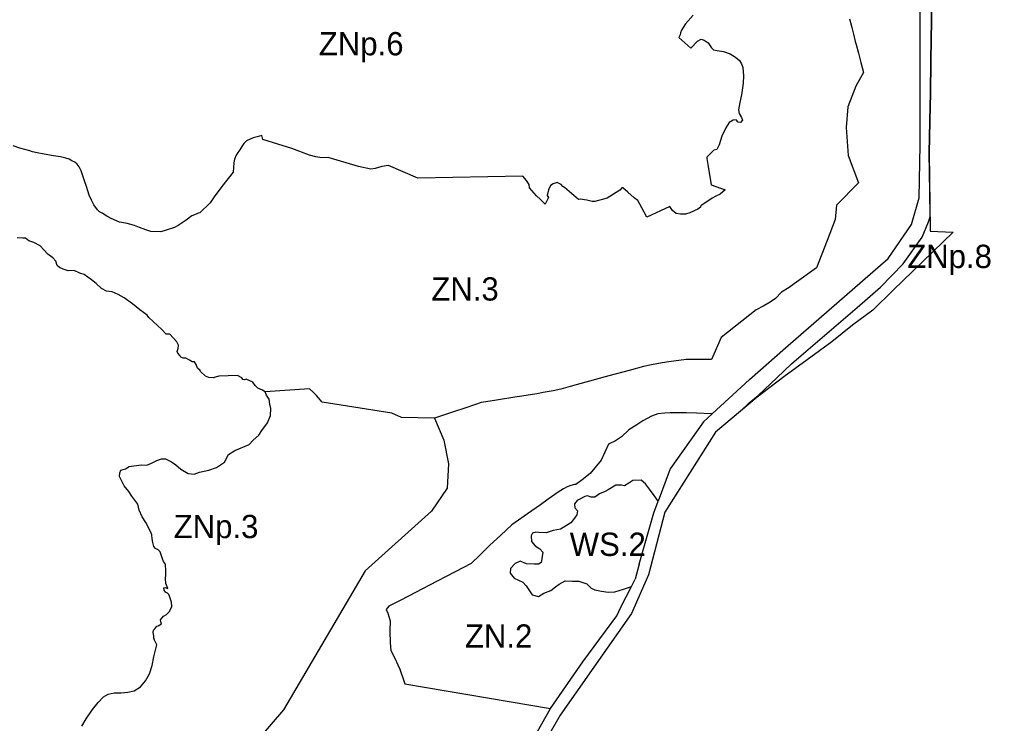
# Model space of a CAD drawing. Extents: x 7421614 to 7422630, y 5544623 to 5545754.
# Drawn here: x 7422069.4 to 7422486.7, y 5545170.9 to 5545473.4 of the extents above; entities that cross this region are included whole.
import ezdxf

# ---------------------------------------------------------------- set-up
doc = ezdxf.new("R2010")
doc.units = 0
for name, color, linetype in [('LIN_Granica Planu', 7, 'Continuous'), ('LIN_Linie Rozgraniczajace', 7, 'Continuous'), ('TXT_Oznaczenia Przeznaczenia', 7, 'Continuous')]:
    doc.layers.add(name, color=color, linetype=linetype)

msp = doc.modelspace()

# ---------------------------------------------------------------- linework, layer by layer
at = {"layer": 'LIN_Granica Planu'}
for p, q in [((7422460.78, 5545436.26), (7422460.37, 5545416.02)), ((7422427.39, 5545342.07), (7422418.45, 5545334.87)), ((7422368.51, 5545296.04), (7422346.72, 5545261.75)), ((7422332.36, 5545218.13), (7422316.17, 5545195.05))]:
    msp.add_line(p, q, dxfattribs=at)
for points in [[(7422461.42, 5545481.65), (7422461.07, 5545455.71), (7422460.88, 5545441.2), (7422460.78, 5545436.26)], [(7422460.37, 5545416.02), (7422460.82, 5545382.36), (7422470.69, 5545382.03), (7422453.28, 5545365.28), (7422444.93, 5545357.05)], [(7422444.93, 5545357.05), (7422436.2, 5545348.51), (7422427.39, 5545342.07)], [(7422418.45, 5545334.87), (7422407.86, 5545327.11), (7422397.93, 5545319.79)], [(7422397.93, 5545319.79), (7422386.41, 5545311.11), (7422368.51, 5545296.04)], [(7422346.72, 5545261.75), (7422339.71, 5545234.8), (7422332.36, 5545218.13)], [(7422316.17, 5545195.05), (7422301.74, 5545174.54), (7422292.28, 5545158.01), (7422284.38, 5545142.54)]]:
    msp.add_lwpolyline(points, dxfattribs=at)
at = {"layer": 'LIN_Linie Rozgraniczajace'}
for p, q in [((7422363.33, 5545300.54), (7422367.05, 5545303.95)), ((7422342.05, 5545261.33), (7422343.92, 5545266.38)), ((7422335.75, 5545239.39), (7422342.05, 5545261.33)), ((7422335.75, 5545239.39), (7422334.03, 5545232.88))]:
    msp.add_line(p, q, dxfattribs=at)
for points in [[(7422367.05, 5545303.95), (7422383.15, 5545318.71), (7422398.64, 5545332.29), (7422442.74, 5545370.72), (7422452.73, 5545385.22), (7422455.99, 5545396.69), (7422456.5, 5545419.48), (7422456.51, 5545483.33), (7422455.04, 5545509.49), (7422458.65, 5545526.65)], [(7422460.73, 5545388.57), (7422460.59, 5545399.19), (7422460.37, 5545416.02), (7422460.78, 5545436.26), (7422460.88, 5545441.2), (7422461.07, 5545455.71), (7422461.42, 5545481.65), (7422460.34, 5545503.62), (7422459.49, 5545515.13), (7422458.65, 5545526.65)], [(7422358.86, 5545475.17), (7422355.63, 5545471.42), (7422353.87, 5545468.71), (7422353.46, 5545467.56), (7422353.3, 5545466.78), (7422352.8, 5545465.63), (7422357.97, 5545461.05), (7422357.99, 5545461.07), (7422360.74, 5545463.97), (7422362.33, 5545464.82), (7422363.71, 5545464.4), (7422365.3, 5545463.29), (7422366.75, 5545461.15), (7422367.62, 5545460.32), (7422369.3, 5545459.95), (7422372.03, 5545459.55), (7422374.85, 5545458.61), (7422377.15, 5545457.12), (7422378.8, 5545455.66), (7422379.73, 5545454.24), (7422380.26, 5545452.67), (7422380.57, 5545449.1), (7422380.41, 5545446.03), (7422379.67, 5545440.91), (7422379.04, 5545437.7), (7422378.46, 5545434.53), (7422378.64, 5545432.97), (7422379.67, 5545431.16), (7422380.07, 5545430.04), (7422379.2, 5545429.06), (7422378.31, 5545429.26), (7422377.44, 5545430.17), (7422376.05, 5545430.03), (7422374.45, 5545429.1), (7422372.92, 5545426.8), (7422371.31, 5545423.19), (7422370.1, 5545419.47), (7422369.07, 5545417.52), (7422367.82, 5545417.2), (7422364.78, 5545414.21), (7422364.8, 5545413.67), (7422365.27, 5545411.09), (7422366.66, 5545402.3), (7422372.67, 5545400.15), (7422370.49, 5545398.35), (7422368.61, 5545397.45), (7422367.09, 5545396.56), (7422362.29, 5545393.26), (7422362.03, 5545392.66), (7422360.88, 5545391.84), (7422357.55, 5545390.27), (7422355.62, 5545389.72), (7422353.51, 5545389.64), (7422351.62, 5545390.03), (7422350.02, 5545391.26), (7422348.88, 5545392.96), (7422338.96, 5545388.41), (7422336.92, 5545392.39), (7422335.09, 5545395.57), (7422333.57, 5545396.69), (7422330.82, 5545399.11), (7422328.65, 5545400.99), (7422328.36, 5545401.22), (7422327.45, 5545400.08), (7422325.86, 5545399.07), (7422321.91, 5545396.61), (7422316.71, 5545395.14), (7422315.48, 5545395.09), (7422313.18, 5545395.7), (7422310.37, 5545396.18), (7422309.62, 5545396.07), (7422303.57, 5545401.16), (7422302.91, 5545401.6), (7422302.16, 5545402.43), (7422300.45, 5545403.35), (7422298.72, 5545402.77), (7422297.67, 5545402.05), (7422296.75, 5545400.21), (7422296.25, 5545397.79), (7422296.74, 5545396.8), (7422295.34, 5545393.99), (7422293.31, 5545396.03), (7422291.58, 5545397.52), (7422288.65, 5545401.06), (7422288.4, 5545402.39), (7422287.37, 5545404.2), (7422285.7, 5545406.01), (7422240.66, 5545405.21), (7422228.01, 5545410.64), (7422225.2, 5545410.13), (7422222.28, 5545409.26), (7422220.34, 5545409.03), (7422215.08, 5545410.11), (7422202.02, 5545413.99), (7422199.33, 5545413.95), (7422196.72, 5545414.35), (7422194.02, 5545415.11), (7422186.51, 5545417.86), (7422180.38, 5545419.78), (7422174.05, 5545421.85), (7422173.52, 5545423.49), (7422171.53, 5545422.93), (7422169.86, 5545422.54), (7422167.01, 5545421.26), (7422165.87, 5545420.13), (7422164.91, 5545418.74), (7422164.13, 5545417.33), (7422163.21, 5545416.17), (7422162.55, 5545415.11), (7422161.88, 5545413.28), (7422161.48, 5545411.76), (7422161.48, 5545411.76), (7422161.19, 5545407.81), (7422156.35, 5545401.56), (7422153.05, 5545397.17), (7422151.39, 5545394.61), (7422146.89, 5545390.26), (7422146.27, 5545390.07), (7422145.65, 5545389.89), (7422144.58, 5545389.46), (7422143.5, 5545389.04), (7422141.01, 5545387.1), (7422137.66, 5545384.84), (7422135.99, 5545383.98), (7422135.99, 5545383.98), (7422132.47, 5545382.79), (7422130.12, 5545382.18), (7422125.87, 5545382.23), (7422123.68, 5545382.91), (7422120.94, 5545384.03), (7422118.9, 5545384.84), (7422115.73, 5545385.66), (7422113.43, 5545386.08), (7422112.39, 5545386.32), (7422108.79, 5545387.89), (7422107.02, 5545388.85), (7422104.9, 5545390.12), (7422103.74, 5545390.76), (7422102.93, 5545391.58), (7422101.34, 5545393.69), (7422100.32, 5545395.72), (7422099.34, 5545397.9), (7422098.25, 5545401.57), (7422097.41, 5545403.95), (7422095.9, 5545408.29), (7422095.07, 5545410.01), (7422094.17, 5545411.21), (7422093.16, 5545412.08), (7422091.9, 5545412.66), (7422090.8, 5545413.28), (7422089.27, 5545413.78), (7422087.11, 5545414.27), (7422085.09, 5545414.57), (7422084.06, 5545414.73), (7422080, 5545415.47), (7422076.98, 5545416.04), (7422074.96, 5545416.42), (7422073.84, 5545416.88), (7422069.54, 5545418.05), (7422066.66, 5545419.08)], [(7422426.09, 5545473.68), (7422426.47, 5545472.06), (7422427.08, 5545469.85), (7422427.88, 5545466.98), (7422428.57, 5545463.93), (7422428.99, 5545462.57), (7422429.92, 5545458.87), (7422430.93, 5545454.82), (7422431.56, 5545452.64), (7422432.07, 5545450.53), (7422428.79, 5545444.7), (7422425.32, 5545435.83), (7422424.65, 5545426.9), (7422425.5, 5545414.85), (7422429.91, 5545403.22), (7422420.46, 5545393.53), (7422419.9, 5545387.42), (7422416.45, 5545378.36), (7422411.91, 5545366.65), (7422402.38, 5545359.78), (7422400.24, 5545358.24), (7422396.83, 5545356.13), (7422394.25, 5545353.41), (7422392.02, 5545351.83), (7422389.34, 5545350.26), (7422385.99, 5545348.67), (7422370.98, 5545336.74), (7422366.76, 5545327.26), (7422355.85, 5545327.3), (7422348.52, 5545326.22), (7422345.64, 5545325.79), (7422341.05, 5545324.93), (7422337.55, 5545324.27), (7422331.48, 5545322.59), (7422322.74, 5545320.23), (7422312.83, 5545317.54), (7422306.1, 5545315.63), (7422302.06, 5545314.59), (7422298.78, 5545313.75), (7422294.5, 5545313.02), (7422291.69, 5545312.55), (7422285.27, 5545311.56), (7422282.25, 5545311.1), (7422274.42, 5545309.77), (7422269.82, 5545309.08), (7422267.78, 5545308.78), (7422265.43, 5545307.98), (7422261.17, 5545306.53), (7422255.93, 5545304.85), (7422247.74, 5545302.11)], [(7422379.22, 5545305.05), (7422382.95, 5545308.63), (7422386.83, 5545311.86), (7422394.9, 5545319.46), (7422401.25, 5545325.37), (7422405.38, 5545328.93), (7422429.42, 5545349.57), (7422439.48, 5545358.41), (7422449.1, 5545368.35), (7422457.29, 5545379.8), (7422460.08, 5545386.4), (7422460.73, 5545388.57)], [(7422460.73, 5545388.57), (7422460.82, 5545382.36), (7422470.69, 5545382.03), (7422453.28, 5545365.28), (7422444.93, 5545357.05), (7422436.2, 5545348.51), (7422427.39, 5545342.07), (7422418.45, 5545334.87), (7422407.86, 5545327.11), (7422397.93, 5545319.79), (7422386.41, 5545311.11), (7422379.22, 5545305.05)], [(7422174.99, 5545313.44), (7422173.89, 5545314.06), (7422171.91, 5545314.93), (7422170.71, 5545316.03), (7422169.63, 5545317.58), (7422166.82, 5545318.8), (7422166.17, 5545318.47), (7422165.45, 5545318.66), (7422164.98, 5545319.41), (7422163.12, 5545320.36), (7422155.02, 5545320.04), (7422152.66, 5545319.4), (7422150.75, 5545319.47), (7422149.34, 5545320.12), (7422147.19, 5545322.04), (7422147.06, 5545322.61), (7422145.91, 5545323.59), (7422145.3, 5545325.08), (7422144.6, 5545326.26), (7422143.69, 5545326.29), (7422142.5, 5545327.05), (7422140.94, 5545327.77), (7422139.84, 5545327.84), (7422138.8, 5545328.22), (7422138.44, 5545328.79), (7422137.46, 5545330.02), (7422137.2, 5545330.68), (7422137.62, 5545331.98), (7422137.7, 5545333.38), (7422137.1, 5545334.87), (7422134.04, 5545338.2), (7422132.5, 5545338.16), (7422130.55, 5545340.17), (7422124.99, 5545345.34), (7422124.27, 5545346.35), (7422121.12, 5545348.67), (7422117.96, 5545351.16), (7422114.35, 5545353.69), (7422111.83, 5545355.23), (7422109.19, 5545356.38), (7422106.86, 5545356.67), (7422104.62, 5545357.76), (7422102.3, 5545359.88), (7422100.37, 5545361.43), (7422097.19, 5545363.74), (7422095.36, 5545364.4), (7422092.89, 5545365.54), (7422090.3, 5545365.32), (7422088.14, 5545366.01), (7422086.65, 5545366.73), (7422085.68, 5545367.65), (7422084.98, 5545369.55), (7422083.79, 5545370.94), (7422081.53, 5545372.5), (7422079.84, 5545374.39), (7422078.25, 5545376.06), (7422075.57, 5545377.54), (7422073.49, 5545378.27), (7422072.04, 5545379.46), (7422070.83, 5545379.35), (7422068.45, 5545379.52)], [(7422096.25, 5545169.76), (7422098.02, 5545172.85), (7422100.85, 5545176.85), (7422103.26, 5545179.86), (7422105.48, 5545182.33), (7422107.48, 5545183.5), (7422110.12, 5545184.07), (7422113.12, 5545184.08), (7422115.98, 5545184.4), (7422118.65, 5545184.87), (7422121.39, 5545186.6), (7422123.51, 5545189.17), (7422125.23, 5545192.16), (7422126.5, 5545195.85), (7422127.16, 5545199.51), (7422127.93, 5545202.41), (7422128.37, 5545204.63), (7422127.47, 5545206.74), (7422127.1, 5545207.64), (7422127.15, 5545208.54), (7422126.85, 5545210.01), (7422127.08, 5545210.92), (7422127.55, 5545211.58), (7422128.08, 5545212.19), (7422128.43, 5545212.77), (7422129.08, 5545212.83), (7422130.38, 5545213.69), (7422130.18, 5545214.59), (7422130.07, 5545215.49), (7422131.33, 5545216.98), (7422132.65, 5545217.73), (7422133.82, 5545218.94), (7422134.83, 5545221.15), (7422134.81, 5545223.06), (7422133.95, 5545225.55), (7422133.66, 5545226.34), (7422133.06, 5545226.81), (7422132.22, 5545227.32), (7422131.56, 5545228.14), (7422131.44, 5545229.15), (7422131.86, 5545229.34), (7422133.1, 5545228.84), (7422132.32, 5545231.03), (7422132.21, 5545233.08), (7422132.37, 5545234.83), (7422132.35, 5545236.46), (7422132.19, 5545239.29), (7422131.34, 5545240.54), (7422130.85, 5545241.62), (7422129.94, 5545244.69), (7422129.06, 5545245.53), (7422127.9, 5545246.14), (7422127.21, 5545247), (7422126.66, 5545248.59), (7422126.42, 5545250.17), (7422126.24, 5545251.93), (7422125.76, 5545253.36), (7422123.78, 5545257.21), (7422122.12, 5545259.74), (7422120.85, 5545262.57), (7422120.32, 5545265.18), (7422117.66, 5545268.56), (7422116.36, 5545270.57), (7422114.39, 5545273.02), (7422112.44, 5545276.97), (7422112.49, 5545278.64), (7422113.02, 5545279.69), (7422114.94, 5545280.3), (7422116.5, 5545281.28), (7422121.65, 5545281.96), (7422124.12, 5545281.88), (7422126.17, 5545282.67), (7422128.47, 5545283.93), (7422130.43, 5545284.58), (7422132.18, 5545284.55), (7422134.73, 5545283.36), (7422136.64, 5545281.95), (7422138.76, 5545280.09), (7422141.92, 5545278.35), (7422144.43, 5545278.04), (7422146.84, 5545278.92), (7422150.8, 5545279.68), (7422154.03, 5545280.84), (7422157.46, 5545283.12), (7422159.23, 5545286.46), (7422161.98, 5545288.14), (7422168.17, 5545290.76), (7422169.82, 5545292.59), (7422172.29, 5545294.73), (7422173.61, 5545296.75), (7422175.93, 5545300.1), (7422177.25, 5545303.19), (7422177.49, 5545306.16), (7422176.98, 5545308.04), (7422176.66, 5545310.2), (7422175.53, 5545311.95), (7422174.99, 5545313.44)], [(7422247.74, 5545302.11), (7422233.58, 5545302.4), (7422229.42, 5545304.15), (7422199.48, 5545308.97), (7422197.09, 5545311.79), (7422195.41, 5545313.36), (7422194.02, 5545314.66), (7422174.99, 5545313.44)], [(7422379.22, 5545305.05), (7422368.51, 5545296.04), (7422346.72, 5545261.75), (7422339.71, 5545234.8), (7422332.36, 5545218.13), (7422316.17, 5545195.05), (7422301.74, 5545174.54), (7422292.28, 5545158.01), (7422284.38, 5545142.54), (7422278.94, 5545127.93), (7422270.92, 5545095.19), (7422266.15, 5545080.16), (7422257.17, 5545065.38), (7422234.12, 5545037.96), (7422219.2, 5545020.95), (7422208.14, 5545006.76)], [(7422367.05, 5545303.95), (7422360.33, 5545304.2), (7422356.03, 5545304.37), (7422349.1, 5545304.35), (7422346.77, 5545304.25), (7422343.81, 5545303.86), (7422340.99, 5545302.87), (7422337.32, 5545300.92), (7422334.66, 5545299.13), (7422331.34, 5545297.12), (7422328.16, 5545294.07), (7422325.61, 5545292.36), (7422322.5, 5545290.9), (7422319.44, 5545284.06), (7422314.66, 5545278.28), (7422311.16, 5545275.51), (7422308.44, 5545273.61), (7422307.86, 5545273.58), (7422306.35, 5545273.09), (7422304.84, 5545272.59), (7422303.19, 5545271.76), (7422300.92, 5545270.23), (7422296.67, 5545267.33), (7422293.34, 5545264.87), (7422287.76, 5545260.99), (7422282.47, 5545257.31), (7422281, 5545256.29), (7422276.23, 5545251.85), (7422271.46, 5545247.41), (7422267.19, 5545243.27), (7422263.55, 5545239.62), (7422256.63, 5545236.04), (7422248.9, 5545232.03), (7422239.63, 5545227.23), (7422233.26, 5545223.93), (7422228.12, 5545221.27), (7422226.96, 5545219.83), (7422227.73, 5545218.34), (7422228.66, 5545215.06), (7422228.52, 5545210.57), (7422228.75, 5545205.6), (7422229, 5545202.2), (7422230.67, 5545198.98), (7422231.99, 5545196.03), (7422232.81, 5545194.18), (7422234.62, 5545189.21), (7422235.07, 5545187.98), (7422297.62, 5545177.29)], [(7422247.74, 5545302.11), (7422251.81, 5545292.57), (7422253.78, 5545282.38), (7422253.25, 5545272.02), (7422246.41, 5545262.11), (7422217.9, 5545236.43), (7422182.85, 5545176.71), (7422160.75, 5545151.12), (7422105.13, 5545094.82), (7422092.03, 5545088.33), (7422090.99, 5545087.63), (7422089.52, 5545086.84), (7422088.09, 5545086.6), (7422082.36, 5545089.7), (7422070.87, 5545095.79), (7422070, 5545096.25)], [(7422363.33, 5545300.54), (7422349.05, 5545280.25), (7422343.92, 5545266.38)], [(7422343.92, 5545266.38), (7422342.12, 5545268.82), (7422340.09, 5545271.59), (7422338.42, 5545273.87), (7422336.51, 5545275.36), (7422333, 5545275.22), (7422331.22, 5545274.1), (7422329.43, 5545272.98), (7422328.08, 5545273.3), (7422325.76, 5545273.32), (7422322.33, 5545271.27), (7422321.08, 5545270.53), (7422318.61, 5545269.5), (7422316.71, 5545268.12), (7422315.05, 5545268.09), (7422313.52, 5545268.72), (7422312.36, 5545268.44), (7422309.89, 5545267.12), (7422309.07, 5545266.69), (7422307.95, 5545265.33), (7422308.1, 5545263.58), (7422309.24, 5545262.24), (7422308.94, 5545260.51), (7422307.89, 5545259.1), (7422306.34, 5545257.03), (7422304.11, 5545255.71), (7422301.88, 5545254.39), (7422298.78, 5545253.82), (7422295.8, 5545252.78), (7422292.65, 5545252.95), (7422291.27, 5545253.03), (7422289.93, 5545252.7), (7422289.35, 5545251.45), (7422289.4, 5545249.04), (7422290.97, 5545247.23), (7422292.97, 5545245.89), (7422294.27, 5545244.55), (7422294.01, 5545242.69), (7422293.75, 5545240.84), (7422293.64, 5545240.07), (7422292.44, 5545239.33), (7422290.54, 5545239.4), (7422287.27, 5545239.53), (7422284.61, 5545240.58), (7422282.41, 5545239.56), (7422280.49, 5545237.51), (7422280.23, 5545235.49), (7422282.07, 5545233.29), (7422285.79, 5545231.58), (7422287.19, 5545230.07), (7422288.58, 5545227.93), (7422289.79, 5545226.16), (7422292.42, 5545225.46), (7422294.78, 5545226.82), (7422297.7, 5545228.04), (7422299.79, 5545229.61), (7422301.28, 5545230.72), (7422303.98, 5545232.15), (7422306.92, 5545232.1), (7422309.85, 5545232.04), (7422311.56, 5545231.47), (7422313.3, 5545230.87), (7422315.08, 5545229.04), (7422316.71, 5545228.27), (7422319.57, 5545227.78), (7422322.44, 5545227.29), (7422325.33, 5545227.46), (7422328.95, 5545228.56), (7422332.46, 5545229.79)], [(7422297.62, 5545177.29), (7422311.53, 5545197.31), (7422326.05, 5545217.17), (7422327.91, 5545220.83), (7422332.46, 5545229.79)], [(7422332.46, 5545229.79), (7422334.03, 5545232.88)], [(7422205.48, 5545011.59), (7422214.94, 5545022.33), (7422230.51, 5545041.31), (7422253.33, 5545067.49), (7422261.4, 5545082.99), (7422266.67, 5545096.33), (7422271.86, 5545115.08), (7422274.82, 5545129.1), (7422280.04, 5545144.12), (7422288.34, 5545160.89), (7422297.62, 5545177.29)]]:
    msp.add_lwpolyline(points, dxfattribs=at)

# ---------------------------------------------------------------- texts
at = {"layer": 'TXT_Oznaczenia Przeznaczenia'}
for s, p in [('ZNp.6', (7422198.05, 5545457.94)), ('       ZNp.8', (7422424.89, 5545366.56)), ('ZN.3', (7422246.4, 5545352.59)), ('ZNp.3', (7422135.68, 5545250.53)), ('WS.2', (7422305.88, 5545242.88)), ('ZN.2', (7422260.82, 5545203.47))]:
    msp.add_text(s, height=10, dxfattribs=at).set_placement(p)

doc.saveas('drawing.dxf')
